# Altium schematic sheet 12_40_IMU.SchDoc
size 289 x 396 mm
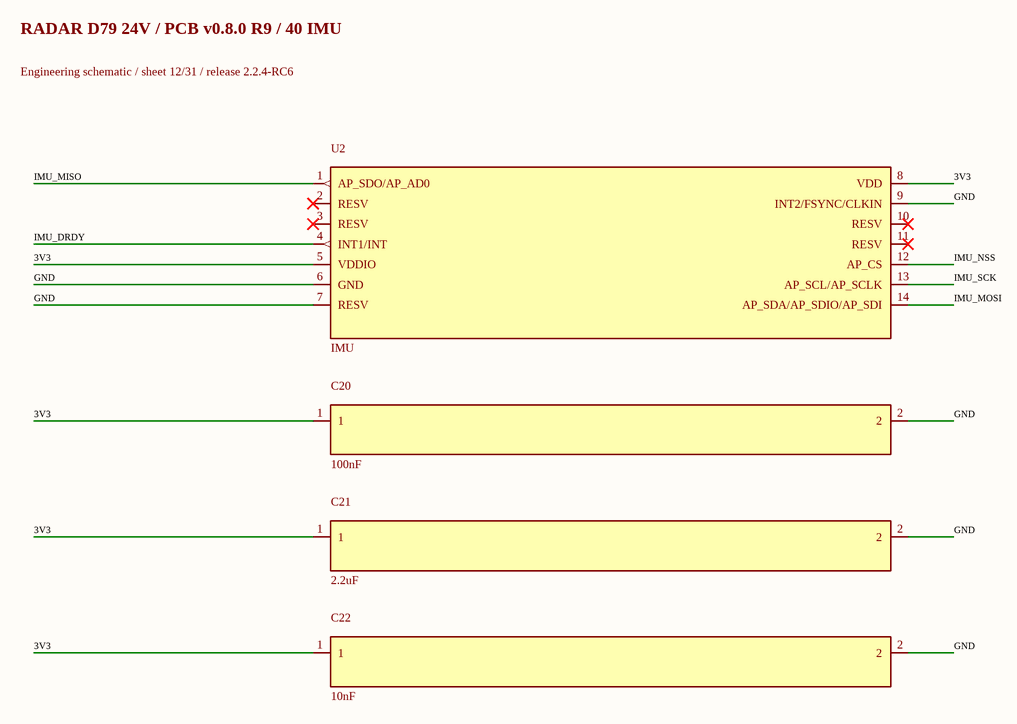
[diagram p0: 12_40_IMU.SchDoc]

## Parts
C20  100nF  [C_0402_1005Metric]
C21  2.2uF  [C_0603_1608Metric]
C22  10nF  [C_0402_1005Metric]
U2  IMU  [ICM-42688-P_LGA14_2.5x3mm_P0.5mm]

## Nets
3V3: C20.1 C21.1 C22.1 U2.5(VDDIO) U2.8(VDD)
GND: C20.2 C21.2 C22.2 U2.6(GND) U2.7(RESV) U2.9(INT2/FSYNC/CLKIN)
IMU_DRDY: U2.4(INT1/INT)
IMU_MISO: U2.1(AP_SDO/AP_AD0)
IMU_MOSI: U2.14(AP_SDA/AP_SDIO/AP_SDI)
IMU_NSS: U2.12(AP_CS)
IMU_SCK: U2.13(AP_SCL/AP_SCLK)

Not connected (* = marked no-connect by the designer): U2 2(RESV)* 3(RESV)* 10(RESV)* 11(RESV)*

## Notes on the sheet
- RADAR D79 24V / PCB v0.8.0 R9 / 40 IMU
- Engineering schematic / sheet 12/31 / release 2.2.4-RC6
